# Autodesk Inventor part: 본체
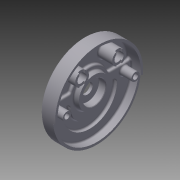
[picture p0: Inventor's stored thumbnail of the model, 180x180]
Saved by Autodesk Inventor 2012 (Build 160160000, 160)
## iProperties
Created: 2015-04
Part Number: 본체
Material: 알루미늄-6061
Document SubType Name: Modeling
Designer: Owner
Density: 2.71 g/cm^3
Mass: 899.843 g
Surface Area: 1054.84 cm^2
Volume: 332.045 cm^3
Author: Owner
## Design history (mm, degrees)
sketch "스케치2"
  geometry: C1 r 95 at (0, 0); 1 further point
  constraints: 1 centre point, 1 coincident
  dimensions: "d3" = 190 diameter of C1
extrude "돌출1" new body sketch "스케치2" distance "d4" = 32; taper "d5" = 0 deg
sketch "스케치3"
  geometry: C1 r 95 at (0, 0) reference; C2 r 90 at (0, 0)
  constraints: 1 centre point, 1 coincident
  dimensions: "d6" = 180 diameter of C2
extrude "돌출2" cut sketch "스케치3" distance "d7" = 20.5; taper "d8" = 0 deg
sketch "스케치4"
  geometry: L1 (-79.667, -14)-(79.667, -14); C1 r 90 at (0, 0) reference; C2 r 90 at (0, 0) reference; C3 r 90 at (0, 0) reference; C4 r 95 at (0, 0) reference; A1 r 41 centre (0, -14) between (-41, -14) and (41, -14); A2 r 59 centre (0, -14) between (-59, -14) and (59, -14); A3 r 9 centre (-50, -14) between (-41, -14) and (-59, -14); A4 r 9 centre (50, -14) between (59, -14) and (41, -14); 1 further point
  constraints: 8 point on circle, 4 centre point, 2 coincident, 2 end point, 2 point on line, 2 tangent, 1 horizontal, 1 midpoint, 1 vertical alignment
  dimensions: "d9" = 14 distance from line of C1.centre L1; "d10" = 82 diameter of A1; "d11" = 118 diameter of A2; "d12" = 18 diameter of A3; "d13" = 18 diameter of A4
extrude "돌출3" cut sketch "스케치4" distance "d14" = 7; taper "d15" = 0 deg
sketch "스케치5"
  geometry: L1 (-83.283, 12)-(83.283, 12); C1 r 90 at (0, 0) reference; A1 r 42 centre (0, 0) between (40.249, 12) and (-40.249, 12); A2 r 5 centre (-83.283, 17) between (-88.182, 18) and (-83.283, 12); A3 r 5 centre (83.283, 17) between (83.283, 12) and (88.182, 18); A4 r 90 centre (0, 0) between (-88.182, 18) and (88.182, 18) reference; A5 r 5 centre (-43.818, 17) between (-43.818, 12) and (-39.156, 15.191); A6 r 5 centre (43.818, 17) between (39.156, 15.191) and (43.818, 12); A7 r 90 centre (0, 0) between (88.182, 18) and (-88.182, 18)
  constraints: 16 point on circle, 8 tangent, 6 centre point, 4 point on line, 2 coincident, 2 end point, 1 horizontal
  dimensions: "d16" = 84 diameter of A1; "d17" = 12 distance from line of L1 A1.centre; "d18" = 10 diameter of A2; "d19" = 10 diameter of A3; "d20" = 10 diameter of A5; "d21" = 10 diameter of A6
extrude "돌출4" cut sketch "스케치5" distance "d22" = 7; taper "d23" = 0 deg
sketch "스케치6"
  geometry: L1 (-83.283, 12)-(-43.818, 12) reference; L2 (-56.202, 52)-(58.852, 52); L3 (0, 0)-(0, 134.318); C1 r 15 at (-40, 52); A1 r 42 centre (0, 0) between (39.156, 15.191) and (-39.156, 15.191) reference; A2 r 90 centre (0, 0) between (88.182, 18) and (-88.182, 18) reference
  constraints: 4 end point, 1 centre point, 1 parallel, 1 perpendicular, 1 point on line
  dimensions: "d24" = 52 distance from line of L2 A1.centre; "d25" = 30 diameter of C1; "d26" = 40 distance from line of L3 C1.centre
extrude "돌출5" join sketch "스케치6" distance "d27" = 30.5; taper "d28" = 0 deg
sketch "스케치7"
  geometry: C1 r 15 at (0, 0) reference; C2 r 10 at (0, 0); 1 further point
  constraints: 1 centre point, 1 coincident
  dimensions: "d29" = 20 diameter of C2
extrude "돌출6" cut sketch "스케치7" stored distance "d30" = 30.5; taper "d31" = 0 deg
sketch "스케치8"
  geometry: L1 (6, 13.748)-(6, 8); L2 (6, -8)-(6, -13.748); L3 (0, 15)-(0, 10); L4 (0, -10)-(0, -15); L5 (-6, 13.748)-(-6, 8); L6 (-6, -8)-(-6, -13.748); C1 r 10 at (0, 0) reference; C2 r 15 at (0, 0) reference; A1 r 10 centre (0, 0) between (6, 8) and (6, -8); A2 r 15 centre (0, 0) between (-6, 13.748) and (0, 15); 4 further points
  constraints: 12 end point, 12 point on circle, 8 parallel, 3 coincident, 2 centre point, 2 concentric, 2 midpoint, 2 vertical, 2 vertical alignment
  dimensions: "d34" = 6 distance between parallel lines of L5 L3; "d35" = 6 distance between parallel lines of L3 L1; "d36" = 6 distance between parallel lines of L4 L2; "d37" = 6 distance between parallel lines of L6 L4
extrude "돌출7" cut sketch "스케치8" distance "d38" = 3; taper "d39" = 0 deg
sketch "스케치9"
  geometry: C1 r 35 at (0, 0); A1 r 90 centre (0, 0) between (-88.182, 18) and (88.182, 18) reference
  constraints: 1 centre point, 1 coincident
  dimensions: "d40" = 70 diameter of C1
extrude "돌출8" join sketch "스케치9" distance "d41" = 10; taper "d42" = -10 deg
hole "구멍1" diameter "d45" = 23; stored, may be unused: countersink angle "d49" = 90 deg, drill point angle "d51" = 118 deg; dims "d43" = 10, "d44" = 10, "d46" = 6, "d47" = 50, "d48" = 15, "d50" = 8
sketch "스케치10"
  geometry: L1 (-43.818, 12)-(-83.283, 12) reference; L2 (-83.283, 0)-(79.95, 0); C1 r 9 at (-74, 0); C2 r 9 at (74, 0); A1 r 90 centre (0, 0) between (-88.182, 18) and (88.182, 18) reference; A2 r 15 centre (-40, 52) between (-46, 65.748) and (-46, 38.252) reference; A3 r 74 centre (0, 0) between (-74, 0) and (74, 0)
  constraints: 3 centre point, 2 end point, 2 point on circle, 2 point on line, 1 coincident, 1 parallel
  dimensions: "d52" = 52 distance from line of A2.centre L2; "d53" = 148 diameter of A3; "d54" = 18 diameter of C1; "d55" = 18 diameter of C2
extrude "돌출9" join sketch "스케치10" distance "d56" = 25; taper "d57" = 0 deg
hole "구멍2" diameter "d60" = 11; stored, may be unused: countersink angle "d64" = 90 deg, drill point angle "d66" = 0 deg; dims "d58" = 10, "d59" = 10, "d61" = 6, "d62" = 18, "d63" = 15, "d65" = 11
sketch "스케치11"
  geometry: C1 r 5.5 at (74, 0) reference; C2 r 9 at (74, 0)
  constraints: 1 centre point, 1 coincident
  dimensions: "d67" = 18 diameter of C2
extrude "돌출10" cut sketch "스케치11" distance "d68" = 11; taper "d69" = 0 deg
sketch "스케치12"
  geometry: C1 r 9 at (0, 0) reference; C2 r 5.5 at (0, 0); 1 further point
  constraints: 1 centre point, 1 coincident
  dimensions: "d70" = 11 diameter of C2
extrude "돌출11" cut sketch "스케치12" stored distance "d71" = 11; taper "d72" = 0 deg
sketch "스케치13"
  geometry: C1 r 5.5 at (-74, 0) reference; C2 r 9 at (-74, 0)
  constraints: 1 centre point, 1 coincident
  dimensions: "d73" = 18 diameter of C2
extrude "돌출12" cut sketch "스케치13" distance "d74" = 11; taper "d75" = 0 deg
sketch "스케치14"
  geometry: L1 (0, 0)-(0, -72); L2 (0, 0)-(-8.132, -8.132); L3 (-36.062, -36.062)-(-50.912, -50.912); L4 (0, 0)-(8.132, -8.132); L5 (36.062, -36.062)-(50.912, -50.912); C1 r 95 at (0, 0) reference; A1 r 11.5 centre (0, 0) between (-8.132, -8.132) and (8.132, -8.132) reference; A2 r 72 centre (0, 0) between (0, -72) and (-50.912, -50.912); A3 r 51 centre (0, 0) between (-36.062, -36.062) and (36.062, -36.062)
  constraints: 10 end point, 7 point on circle, 2 centre point, 2 coincident, 1 vertical
  dimensions: "d76" = 144 diameter of A2; "d77" = 102 diameter of A3; "d80" = 45 deg angle of L1 L5; "d81" = 45 deg angle of L1 L3
extrude "돌출13" join sketch "스케치14" distance "d82" = 5; taper "d83" = 0 deg
sketch "스케치15"
  geometry: C1 r 88 at (0, 0); A1 r 72 centre (0, 0) between (-50.912, -50.912) and (50.912, -50.912) reference; A2 r 51 centre (0, 0) between (-36.062, -36.062) and (36.062, -36.062) reference
  constraints: 1 centre point, 1 coincident, 1 other
  dimensions: "d84" = 176 diameter of C1
extrude "돌출14" join sketch "스케치15" distance "d85" = 0.5; taper "d86" = 0 deg
fillet "모깎기1" dims "d87" = 5
fillet "모깎기2" dims "d88" = 4
chamfer "모따기1" distance "d89" = 1; stored, may be unused: second distance "d90" = 2, angle "d91" = 45 deg
chamfer "모따기2" distance "d92" = 1; stored, may be unused: second distance "d93" = 2, angle "d94" = 45 deg
fillet "모깎기3" dims "d95" = 5
sketch "스케치16"
  geometry: L1 (-95, 0)-(95, 0); L2 (0, 0)-(-94.638, -8.28); L3 (0, 0)-(94.638, -8.28); C1 r 90 at (0, 0) reference; A1 r 95 centre (0, 0) between (-94.638, -8.28) and (94.638, -8.28) reference; A2 r 95 centre (0, 0) between (95, 0) and (-95, 0); A3 r 95 centre (0, 0) between (-94.638, -8.28) and (94.638, -8.28); A4 r 90 centre (0, 0) between (90, 0) and (-90, 0); A5 r 90 centre (0, 0) between (-89.658, -7.844) and (89.658, -7.844)
  constraints: 10 point on circle, 6 end point, 4 centre point, 4 point on line, 3 coincident, 1 horizontal
  dimensions: "d96" = 5 deg angle of L1 L2; "d97" = 5 deg angle of L1 L3
extrude "돌출15" cut sketch "스케치16" distance "d98" = 5; taper "d99" = 0 deg
fillet "모깎기4" dims "d100" = 3
fillet "모깎기5" dims "d101" = 0.3
fillet "모깎기6" dims "d102" = 3
fillet "모깎기7" dims "d103" = 3
fillet "모깎기8" dims "d104" = 3
fillet "모깎기9" dims "d105" = 3
fillet "모깎기10" dims "d106" = 3
fillet "모깎기11" dims "d107" = 1
node "솔리드2"
mirror "대칭1"
node "투영된 루프1"
other parameters: "d32" = 6, "d33" = 6, "d78" = 45 deg, "d79" = 45 deg
